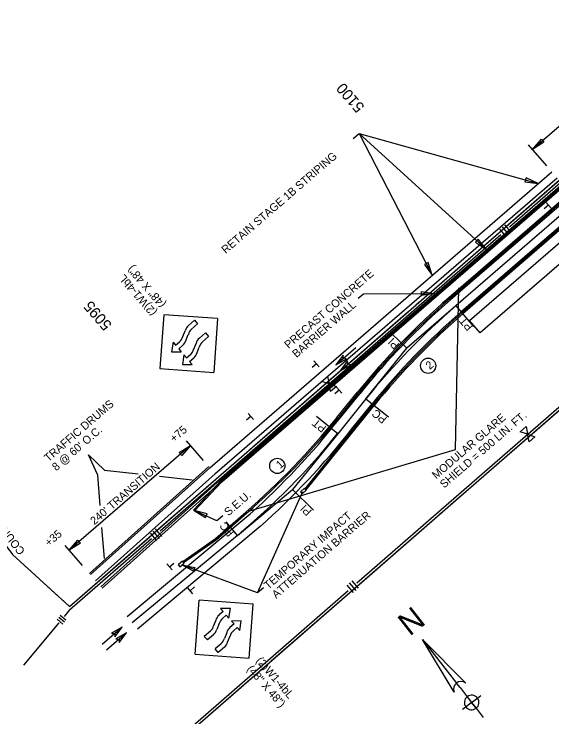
# Model space of a CAD drawing. Extents: x 259983 to 267998, y 211467 to 219827.
# Drawn here: x 262447 to 263253, y 216417 to 217470 of the extents above; entities that cross this region are included whole.
import ezdxf

# ---------------------------------------------------------------- set-up
doc = ezdxf.new("R2010")
doc.units = 0
for name, color, linetype in [('1', 7, 'Continuous'), ('Level 1', 7, 'Continuous'), ('Level 43', 7, 'Continuous'), ('Level 58', 7, 'Continuous'), ('R-W - CofA', 7, 'Continuous'), ('R_MOT', 7, 'Continuous'), ('R_MOT STAGE 1', 7, 'Continuous'), ('R_MOT STAGE 2', 7, 'Continuous'), ('STATIONING1', 7, 'Continuous')]:
    doc.layers.add(name, color=color, linetype=linetype)

msp = doc.modelspace()

# ---------------------------------------------------------------- linework, layer by layer
at = {"layer": '1'}
for p, q in [((262954.9, 217283.9), (262963.8, 217291.6)), ((262963.8, 217291.6), (263232.1, 217216.3)), ((263108.3, 216817.7), (263113, 217059.9)), ((262800.3, 216725.9), (263108.3, 216817.7)), ((262811.6, 216602.6), (262879.6, 216754.7)), ((262750.9, 216710.5), (262716.8, 216726.4)), ((262759.8, 216718.2), (262750.9, 216710.5)), ((262811.6, 216602.6), (262698.3, 216644.7)), ((262820.4, 216610.2), (262811.6, 216602.6))]:
    msp.add_line(p, q, dxfattribs=at)
for points in [[(263240.7, 217278.2), (263223.8, 217267.5), (263236.8, 217282.8)], [(263212.3, 217218.9), (263232.1, 217216.3), (263214, 217224.7)], [(263138, 217128.5), (263154.6, 217117.4), (263142, 217133)], [(263061.8, 217095.2), (263073.5, 217079), (263067.1, 217097.9)], [(263057.1, 217054.3), (263076.9, 217051.3), (263057.1, 217048.3)], [(262694.1, 216813), (262711.1, 216823.7), (262698.1, 216808.5)], [(262736, 216721), (262716.8, 216726.4), (262733.5, 216715.5)], [(262546.6, 216677.3), (262529.6, 216666.6), (262542.6, 216681.8)], [(262715.9, 216635), (262698.3, 216644.7), (262717.9, 216640.6)]]:
    msp.add_lwpolyline(points, close=True, dxfattribs=at)
for points in [[(262962.3, 217044.4), (262970.2, 217051.2), (263076.9, 217051.3)], [(262576.1, 216733.9), (262572.7, 216779), (262558.4, 216809.5), (262582.5, 216786.8), (262633.1, 216781.2)], [(262665, 216777.7), (262713.9, 216772.3)], [(262582.3, 216654), (262578.7, 216700.7)]]:
    msp.add_lwpolyline(points, dxfattribs=at)
at = {"layer": 'Level 1'}
for p, q in [((263058.7, 216532.7), (263123.6, 216467.3)), ((263106.4, 216453.9), (263058.7, 216532.7)), ((263058.7, 216532.7), (263109.6, 216467.5)), ((263115, 216460.6), (263109.6, 216467.5)), ((263115, 216460.6), (263125.7, 216446.9)), ((263125.7, 216446.9), (263132.4, 216438.3)), ((263132.4, 216438.3), (263141, 216445)), ((263141, 216445), (263146.2, 216449)), ((263141, 216445), (263141, 216445)), ((263132.4, 216438.3), (263124.1, 216431.8)), ((263132.4, 216438.3), (263139.1, 216429.8)), ((263139.1, 216429.8), (263132.4, 216438.3)), ((263123.5, 216431.4), (263118.7, 216427.6)), ((263139.1, 216429.8), (263149.8, 216416))]:
    msp.add_line(p, q, dxfattribs=at)
for centre, radius, start, end in [((263116.5, 216458.7), 11.2, 128, 205.3196), ((263116.5, 216458.7), 11.2, 50.6804, 128), ((263132.4, 216438.3), 10.9, 128, 218), ((263132.4, 216438.3), 10.9, 38, 128), ((263132.4, 216438.3), 10.9, 308, 38), ((263132.4, 216438.3), 10.9, 218, 308)]:
    msp.add_arc(centre, radius, start, end, dxfattribs=at)
at = {"layer": 'Level 43'}
for points in [[(262928.8, 216944.5), (262958.8, 216970.5)], [(262935.3, 216935.8), (262965.4, 216961.8)], [(262609, 216551.5), (262579, 216525.5)], [(262615.6, 216542.8), (262585.6, 216516.8)]]:
    msp.add_lwpolyline(points, dxfattribs=at)
at = {"layer": 'Level 58'}
for points in [[(262939.9, 216959.2), (262928.8, 216944.5), (262944.8, 216953.5), (262940.1, 216954.4)], [(262946.5, 216950.4), (262935.3, 216935.8), (262951.4, 216944.8), (262946.7, 216945.6)], [(262597.9, 216536.9), (262609, 216551.5), (262593, 216542.5), (262597.7, 216541.6)], [(262604.4, 216528.1), (262615.6, 216542.8), (262599.5, 216533.8), (262604.2, 216532.9)]]:
    msp.add_lwpolyline(points, close=True, dxfattribs=at)
at = {"layer": 'R-W - CofA'}
for p, q in [((263177.9, 217151.3), (263187.5, 217140.2)), ((263181.6, 217154.5), (263191.2, 217143.4)), ((263174.2, 217148.1), (263183.8, 217137)), ((262908, 216919.6), (262916.7, 216927.1)), ((262918.9, 216915.9), (262908, 216919.6)), ((262916.7, 216927.1), (262918.9, 216915.9)), ((262921.1, 216904.6), (262918.9, 216915.9)), ((262918.9, 216915.9), (262929.8, 216912.1)), ((262929.8, 216912.1), (262921.1, 216904.6)), ((263205.2, 216844.2), (263213.9, 216851.9)), ((263213.9, 216851.9), (263216.2, 216840.5)), ((263216.2, 216840.5), (263205.2, 216844.2)), ((263218.4, 216829.1), (263216.2, 216840.5)), ((263216.2, 216840.5), (263227.2, 216836.7)), ((263227.2, 216836.7), (263218.4, 216829.1)), ((262658.2, 216698.5), (262667.9, 216687.4)), ((262650.9, 216692.1), (262660.5, 216681)), ((262654.6, 216695.3), (262664.2, 216684.2)), ((262945.3, 216614.3), (262955, 216603.1)), ((262949, 216617.5), (262958.8, 216606.4)), ((262952.7, 216620.8), (262962.5, 216609.6)), ((262519.9, 216555.9), (262511.6, 216563)), ((262522.3, 216558.7), (262513.9, 216565.7)), ((262524.6, 216561.5), (262516.2, 216568.5))]:
    msp.add_line(p, q, dxfattribs=at)
for points in [[(262530.1, 216582.3), (263549.4, 217470.5)], [(263189.3, 217151.5), (263403.3, 217338)], [(262694.2, 216380.4), (263719.6, 217273.9)], [(263186.7, 217154.5), (263303.1, 217255.8)], [(262923.2, 216919.6), (263176.1, 217140)], [(263057.2, 217041.5), (263173.5, 217142.9)], [(263220.6, 216844.3), (263476.1, 217067)], [(263048.9, 217034.4), (263053.4, 217038.3)], [(262920.6, 216922.6), (263037, 217023.9)], [(263040.7, 217027.2), (263045.2, 217031.1)], [(263223.1, 216841.3), (263340.7, 216943.8)], [(262666, 216695.5), (262923.2, 216919.6)], [(262800, 216817.4), (262920.6, 216922.6)], [(262960.6, 216617.8), (263220.6, 216844.3)], [(263101.2, 216735), (263223.1, 216841.3)], [(262290.2, 216821.6), (262324.3, 216787.7), (262364.1, 216767.9), (262444.5, 216660.2), (262530.1, 216582.3)], [(262791.7, 216810.3), (262796.2, 216814.2)], [(262783.5, 216803.1), (262788, 216807)], [(262663.4, 216698.5), (262779.8, 216799.8)], [(263092.9, 216727.8), (263097.4, 216731.7)], [(263084.5, 216720.5), (263089.1, 216724.5)], [(262408.4, 216708.5), (262444.5, 216660.2), (262514, 216596.9)], [(262963.2, 216614.8), (263080.8, 216717.3)], [(262533.9, 216585.6), (262650.2, 216686.9)], [(262530, 216577), (262652.8, 216684)], [(262691.6, 216383.4), (262947.2, 216606.1)], [(262832.2, 216500.7), (262949.8, 216603.1)], [(262517.6, 216593.6), (262522, 216589.6)], [(262525.7, 216586.2), (262530.1, 216582.3), (262530.1, 216582.3)], [(262530, 216577), (262521.8, 216567.2)], [(262514.1, 216557.9), (262461.1, 216494.3)], [(262823.9, 216493.4), (262828.4, 216497.4)], [(262815.6, 216486.2), (262820.1, 216490.1)], [(262694.2, 216380.4), (262811.8, 216482.9)]]:
    msp.add_lwpolyline(points, dxfattribs=at)
at = {"layer": 'R_MOT'}
for p, q in [((263247.4, 217183.9), (263241, 217178.3)), ((263243.4, 217188.5), (263251.5, 217179.3)), ((262671.2, 217019.6), (262665.3, 216938.9)), ((262751.9, 217013.9), (262671.2, 217019.6)), ((262751.9, 217013.9), (262746.2, 216933.1)), ((262708.2, 217003.5), (262717.4, 217011.4)), ((262712.9, 216998.1), (262722, 217006)), ((262717.4, 217011.4), (262722, 217006)), ((262699.9, 216986.8), (262703.4, 216995.5)), ((262724.6, 216984.6), (262733.7, 216992.5)), ((262733.7, 216992.5), (262738.3, 216987.1)), ((262704.8, 216981.9), (262708, 216990.1)), ((262729.2, 216979.2), (262738.3, 216987.1)), ((262685.1, 216978.5), (262682.9, 216964.1)), ((262685.1, 216978.5), (262689, 216974)), ((262689, 216974), (262694.7, 216979)), ((262693.7, 216968.7), (262699.8, 216974)), ((262716.2, 216968), (262719.7, 216976.6)), ((262721.1, 216963.1), (262724.3, 216971.2)), ((262682.9, 216964.1), (262697.5, 216964.2)), ((262693.7, 216968.7), (262697.5, 216964.2)), ((262701.4, 216959.7), (262699.3, 216945.2)), ((262701.4, 216959.7), (262705.3, 216955.2)), ((262705.3, 216955.2), (262711.1, 216960.2)), ((262710, 216949.8), (262716.1, 216955.1)), ((262895.8, 216950.7), (262903.8, 216941.4)), ((262699.3, 216945.2), (262713.9, 216945.3)), ((262710, 216949.8), (262713.9, 216945.3)), ((262899.8, 216946.1), (262893.3, 216940.5)), ((262665.3, 216938.9), (262746.1, 216933)), ((262929.9, 216911.2), (262938, 216902)), ((262933.9, 216906.6), (262927.5, 216901)), ((262801.8, 216867.1), (262795.3, 216861.6)), ((262797.8, 216871.7), (262805.8, 216862.5)), ((262684, 216637.1), (262675.9, 216646.4)), ((262680, 216641.7), (262686.4, 216647.3)), ((262715, 216601.3), (262707, 216610.5)), ((262711, 216605.9), (262717.4, 216611.5)), ((262718.3, 216510.7), (262724.1, 216591.5)), ((262804.9, 216585.7), (262724.1, 216591.6)), ((262799.1, 216505), (262804.9, 216585.7)), ((262760.2, 216574.8), (262754.1, 216569.5)), ((262771, 216579.4), (262756.4, 216579.3)), ((262760.2, 216574.8), (262756.4, 216579.3)), ((262768.8, 216564.9), (262771, 216579.4)), ((262749.1, 216561.5), (262745.9, 216553.4)), ((262764.9, 216569.4), (262759.2, 216564.4)), ((262768.8, 216564.9), (262764.9, 216569.4)), ((262787.3, 216560.5), (262772.7, 216560.4)), ((262776.6, 216556), (262772.7, 216560.4)), ((262785.1, 216546.1), (262787.3, 216560.5)), ((262754, 216556.6), (262750.5, 216548)), ((262776.6, 216556), (262770.4, 216550.6)), ((262781.2, 216550.6), (262775.5, 216545.6)), ((262785.1, 216546.1), (262781.2, 216550.6)), ((262741, 216545.4), (262731.9, 216537.5)), ((262745.6, 216540), (262736.5, 216532.1)), ((262765.5, 216542.7), (262762.2, 216534.5)), ((262736.5, 216532.1), (262731.9, 216537.5)), ((262770.3, 216537.8), (262766.9, 216529.1)), ((262757.3, 216526.5), (262748.2, 216518.6)), ((262752.8, 216513.3), (262748.2, 216518.6)), ((262762, 216521.1), (262752.8, 216513.3)), ((262718.3, 216510.7), (262799.1, 216505))]:
    msp.add_line(p, q, dxfattribs=at)
for centre, major_axis in [((262719.6, 216989.8), (-11.6, 13.4)), ((262724.3, 216984.4), (-11.6, 13.4)), ((262683.4, 216992.7), (11.6, -13.4)), ((262688.5, 216987.6), (11.6, -13.4)), ((262735.9, 216971), (-11.6, 13.4)), ((262740.6, 216965.5), (-11.6, 13.4)), ((262699.7, 216973.8), (11.6, -13.4)), ((262704.8, 216968.8), (11.6, -13.4)), ((262765.4, 216555.8), (-11.6, 13.4)), ((262770.5, 216550.8), (-11.6, 13.4)), ((262729.6, 216559.1), (11.6, -13.4)), ((262781.7, 216537), (-11.6, 13.4)), ((262734.3, 216553.6), (11.6, -13.4)), ((262786.8, 216532), (-11.6, 13.4)), ((262745.9, 216540.2), (11.6, -13.4)), ((262750.6, 216534.8), (11.6, -13.4))]:
    msp.add_ellipse(centre, major_axis=major_axis, ratio=0.9, start_param=6.26006, end_param=6.849246, dxfattribs=at)
at = {"layer": 'R_MOT STAGE 1'}
for p, q in [((263565.3, 217449.4), (263098.2, 217045.1)), ((263566.6, 217447.9), (263099.5, 217043.5)), ((263567.9, 217446.4), (263100.8, 217042)), ((263575.8, 217437.4), (263108.7, 217033)), ((263583.6, 217428.3), (263116.5, 217023.9)), ((263585, 217426.8), (263117.8, 217022.4)), ((263586.3, 217425.3), (263119.1, 217020.9)), ((262740, 216790.2), (263252.6, 217234)), ((262747.9, 216781.2), (263260.4, 217224.9)), ((262755.7, 216772.1), (263268.3, 217215.8)), ((262757.1, 216770.6), (263269.6, 217214.3)), ((262758.4, 216769.1), (263270.9, 217212.8)), ((263108.7, 217033), (263035.2, 216969.3)), ((263108.7, 217033), (263135.3, 217002.2)), ((263013.4, 216990.3), (263035.2, 216969.3)), ((262974, 216893.7), (263035.2, 216969.3)), ((262932.3, 216864.2), (262963.2, 216902.5)), ((262933.8, 216863), (262964.7, 216901.2)), ((262974, 216893.7), (262931.8, 216841.3)), ((262974, 216893.7), (263007.8, 216866.4)), ((262882.9, 216758.6), (262984.9, 216884.9)), ((262952.5, 216847.9), (262983.4, 216886.1)), ((262931.8, 216841.3), (262900, 216867)), ((262931.8, 216841.3), (262864.2, 216757.6)), ((262559.8, 216631.7), (262738.5, 216792)), ((262561.3, 216630), (262740, 216790.2)), ((262569.1, 216620.8), (262748.1, 216781.3)), ((262577.1, 216611.9), (262756.1, 216772.4)), ((262579.1, 216609.5), (262757.8, 216769.8)), ((262715.7, 216726.9), (262756.9, 216770.4)), ((262717.1, 216725.5), (262758.4, 216769.1)), ((262758.4, 216769.1), (262756.9, 216770.4)), ((262757.1, 216770.6), (262758.4, 216769.1)), ((262757.1, 216770.6), (262758.4, 216769.1)), ((262781.5, 216688.8), (262864.2, 216757.6)), ((262895.5, 216726.8), (262864.2, 216757.6)), ((262882.9, 216758.6), (262884.5, 216757.3)), ((262884.5, 216757.3), (262883, 216758.7)), ((262800.4, 216720.8), (262616.3, 216566.8)), ((262717.1, 216725.5), (262715.7, 216726.9)), ((262748.9, 216684.3), (262794.1, 216723.7)), ((262750.2, 216682.8), (262795.4, 216722.2)), ((262781.5, 216688.8), (262764.5, 216709.1)), ((262815.8, 216702.4), (262631.7, 216548.4)), ((262781.5, 216688.8), (262624, 216557.6)), ((262699.9, 216649.5), (262748.9, 216684.3)), ((262701, 216648.1), (262750, 216682.6)), ((262750, 216682.6), (262748.9, 216684.3)), ((262750.2, 216682.8), (262748.9, 216684.3)), ((262701.1, 216647.9), (262699.9, 216649.5))]:
    msp.add_line(p, q, dxfattribs=at)
for points in [[(262882.2, 216759.5), (262875.9, 216754.1), (262878.4, 216751.2), (262884.7, 216756.7)], [(262699.1, 216650.1), (262692.8, 216644.6), (262695.3, 216641.8), (262701.6, 216647.3)]]:
    msp.add_lwpolyline(points, close=True, dxfattribs=at)
for centre in [(263067.3, 216943.2), (262841.3, 216793)]:
    msp.add_circle(centre, 11.4, dxfattribs=at)
for centre, radius, start, end in [((263823, 216207.9), 1107.3, 130.8833, 141.0666), ((263823, 216207.9), 1105.3, 130.8833, 141.0666), ((263823, 216207.9), 1103.3, 130.8833, 141.0666), ((263823, 216207.9), 1091.3, 130.8833, 141.0666), ((263823, 216207.9), 1079.3, 130.8833, 141.0666), ((263823, 216207.9), 1077.3, 130.8833, 141.0666), ((263823, 216207.9), 1075.3, 130.8833, 141.0666), ((262051.8, 217575.6), 1131.9, 311.0666, 321.0666), ((262054.6, 217554.4), 1118.5, 311.819, 321.819), ((262052.7, 217556.3), 1145.2, 311.7882, 321.7882), ((262082.8, 217527.2), 1091.3, 309.8056, 321.0666)]:
    msp.add_arc(centre, radius, start, end, dxfattribs=at)
at = {"layer": 'R_MOT STAGE 2'}
for p, q in [((263405.2, 217424.6), (263223.8, 217267.5)), ((263154.6, 217117.4), (262963.8, 217291.6)), ((262963.8, 217291.6), (263073.5, 217079)), ((263245.1, 217242.9), (263217.8, 217274.4)), ((263145, 216992.7), (263129.3, 217010.9)), ((262930.7, 216865.5), (262961.6, 216903.7)), ((262884.5, 216757.3), (262986.5, 216883.6)), ((262711.1, 216823.7), (262529.6, 216666.6)), ((262730.7, 216801), (262705.1, 216830.6)), ((262549.3, 216643.9), (262523.7, 216673.5))]:
    msp.add_line(p, q, dxfattribs=at)
msp.add_lwpolyline([(263567.1, 217342.8), (263559.5, 217351.6), (263145, 216992.7), (263129.3, 217010.9), (263523.1, 217351.7), (263515.2, 217360.8), (263587.5, 217423.8), (263595.6, 217414.5), (263618.9, 217387.6)], close=True, dxfattribs=at)
msp.add_arc((262051.8, 217575.6), 1129.9, 311.0666, 321.0666, dxfattribs=at)

# ---------------------------------------------------------------- texts
at = {"layer": '1'}
for s, rotation, p in [('RETAIN STAGE 1B STRIPING', 40.8733, (262764, 217110.5)), ('PRECAST CONCRETE', 40.8833, (262858.2, 216968.1)), ('BARRIER WALL', 40.8833, (262870, 216954.5)), ('2', 40.8733, (263069.7, 216936.7)), ('TRAFFIC DRUMS', 40.8745, (262498.4, 216798.4)), ('MODULAR GLARE', 40.8733, (263079.4, 216772.6)), ('SHIELD = 500 LIN. FT.', 40.8733, (263091.2, 216759)), ("8 @ 60' O.C.", 40.8745, (262510.2, 216784.8)), ("240' TRANSITION", 40.8733, (262567.4, 216704)), ('1', 40.8733, (262845.6, 216788.1)), ('COUNTY RD. 410', 127.9922, (262464.1, 216665.5)), ('S.E.U.', 40.8733, (262768.1, 216717.2)), ('TEMPORARY IMPACT', 40.8733, (262827.7, 216607.2)), ('ATTENUATION BARRIER', 40.8733, (262839.5, 216593.6))]:
    msp.add_text(s, height=12, rotation=rotation, dxfattribs=at).set_placement(p)
at = {"layer": 'Level 1'}
msp.add_text('N', height=34.2, rotation=38, dxfattribs=at).set_placement((263039.5, 216536.8))
at = {"layer": 'R_MOT'}
for s, rotation, p in [('(48" X 48")', 130.8833, (262675.2, 217036.5)), ('(2)W1-4bL', 130.8833, (262661.6, 217024.1)), ('(2)W1-4bL', 310.8833, (262808.6, 216500.5)), ('(48" X 48")', 310.8833, (262795, 216488.1))]:
    msp.add_text(s, height=12, rotation=rotation, dxfattribs=at).set_placement(p)
at = {"layer": 'R_MOT STAGE 1'}
for s, rotation, p in [('PT', 130.8833, (263135.3, 217002.1)), ('PI', 135.975, (263025, 216975.4)), ('PC', 141.0666, (263006.5, 216864.8)), ('PT', 141.0666, (262915.9, 216851.4)), ('PI', 135.4361, (262893.8, 216725.5)), ('PC', 129.8056, (262777.3, 216693.2))]:
    msp.add_text(s, height=12, rotation=rotation, dxfattribs=at).set_placement(p)
at = {"layer": 'R_MOT STAGE 2'}
for s, p in [('+75', (262686.7, 216827.7)), ('+35', (262499.3, 216671.5))]:
    msp.add_text(s, height=12, rotation=40.8821, dxfattribs=at).set_placement(p)
at = {"layer": 'STATIONING1'}
for s, p in [('5100', (262972.9, 217331.7)), ('5095', (262594.5, 217005))]:
    msp.add_text(s, height=16.5, rotation=130.8833, dxfattribs=at).set_placement(p)

doc.saveas('drawing.dxf')
